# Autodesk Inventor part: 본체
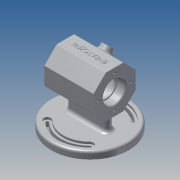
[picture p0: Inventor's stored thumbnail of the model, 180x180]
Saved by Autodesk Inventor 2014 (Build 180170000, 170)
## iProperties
Created: 2017-06
Part Number: 본체
Material: 알루미늄 6061
Document SubType Name: Modeling
Designer: SCD-A14
Density: 2.71 g/cm^3
Appearance: 알루미늄 - 평지
Mass: 562.54 g
Surface Area: 565.529 cm^2
Volume: 207.579 cm^3
Author: SCD-A14
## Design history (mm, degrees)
sketch "스케치1"
  geometry: C1 r 55 at (0, 0); 1 further point
  constraints: 1 centre point, 1 coincident
  dimensions: "d0" = 110 diameter of C1
extrude "돌출1" new body sketch "스케치1" distance "d1" = 10; taper "d2" = 0 deg
sketch "스케치2"
  geometry: L1 (-30, 49.574)-(-30, 74.426); L2 (-30, 74.426)-(-12.426, 92); L3 (-12.426, 92)-(12.426, 92); L4 (12.426, 92)-(30, 74.426); L5 (30, 74.426)-(30, 49.574); L6 (30, 49.574)-(12.426, 32); L7 (12.426, 32)-(-12.426, 32); L8 (-12.426, 32)-(-30, 49.574); L9 (-55, 0)-(55, 0) reference; C1 r 30 at (0, 62); 2 further points
  constraints: 16 end point, 1 centre point, 1 coincident, 1 tangent, 1 vertical, 1 vertical alignment, 17 other
  dimensions: "d3" = 60 diameter of C1; "d4" = 62 distance from line of L9 point (0, 62)
extrude "돌출2" join sketch "스케치2" stored distance "d5" = 70; taper "d6" = 0 deg
sketch "스케치3"
  geometry: L1 (24, 5)-(-24, 5); L2 (-24, 5)-(-24, -5); L3 (-24, -5)-(24, -5); L4 (24, -5)-(24, 5); L5 (24, 5)-(-24, -5); C1 r 5 at (24, 0); C2 r 5 at (-24, 0); 2 further points
  constraints: 10 end point, 3 midpoint, 2 centre point, 2 parallel, 1 coincident, 1 horizontal, 1 perpendicular
  dimensions: "d7" = 48 distance between parallel lines of L2 L4; "d9" = 10 diameter of C1; "d10" = 10 diameter of C2; "d11" = 10 distance between parallel lines of L3 L1
extrude "돌출3" join sketch "스케치3" stored distance "d12" = 70; taper "d13" = 0 deg
sketch "스케치4"
  geometry: L1 (0, 55)-(0, -55) reference; C1 r 16 at (62, 0); 2 further points
  constraints: 1 centre point, 1 horizontal alignment, 1 midpoint
  dimensions: "d14" = 32 diameter of C1; "d15" = 62 distance from line of L1 C1.centre
extrude "돌출4" cut sketch "스케치4" distance "d16" = 12; taper "d17" = 0 deg
sketch "스케치5"
  geometry: C1 r 16 at (0, 0) reference; C2 r 14 at (0, 0); 1 further point
  constraints: 1 centre point, 1 coincident
  dimensions: "d18" = 28 diameter of C2
extrude "돌출5" cut sketch "스케치5" distance "d19" = 3; taper "d20" = 0 deg
sketch "스케치6"
  geometry: C1 r 14 at (-62, 0) reference; C2 r 16 at (-62, 0); 1 further point
  constraints: 1 centre point, 1 coincident
  dimensions: "d21" = 32 diameter of C2
extrude "돌출6" cut sketch "스케치6" distance "d22" = 12; taper "d23" = 0 deg
sketch "스케치7"
  geometry: C1 r 16 at (0, 0) reference; C2 r 16 at (0, 0) reference; C3 r 14 at (0, 0); 1 further point
  constraints: 1 centre point, 1 coincident
  dimensions: "d24" = 28 diameter of C3
extrude "돌출7" cut sketch "스케치7" distance "d25" = 3; taper "d26" = 0 deg
sketch "스케치8"
  geometry: C1 r 14 at (0, 0) reference; C2 r 25 at (0, 0); 1 further point
  constraints: 1 centre point, 1 coincident
  dimensions: "d27" = 50 diameter of C2
extrude "돌출8" cut sketch "스케치8" distance "d28" = 40; taper "d29" = 0 deg
sketch "스케치9"
  geometry: L1 (0, 62)-(0, -16.548); L2 (0, 62)-(26.163, 88.163); L3 (30, 74.426)-(12.426, 92) reference; C1 r 16 at (0, 62) reference; 2 further points
  constraints: 4 end point, 1 coincident, 1 vertical
  dimensions: "d30" = 45 deg angle of L2 L1; "d31" = 7 distance from line of L2.end L3
node "작업 평면1"
sketch "스케치10"
  geometry: C1 r 8 at (0, 0); 2 further points
  constraints: 1 centre point, 1 coincident
  dimensions: "d32" = 16 diameter of C1
extrude "돌출9" join sketch "스케치10" stored distance "d33" = 40; taper "d34" = 0 deg
sketch "스케치11"
  geometry: C1 r 8 at (0, 0) reference; C2 r 4 at (0, 0); 1 further point
  constraints: 1 centre point, 1 coincident
  dimensions: "d35" = 8 diameter of C2
extrude "돌출10" cut sketch "스케치11" stored distance "d36" = 40; taper "d37" = 0 deg
sketch "스케치12" dims "d38" = 10, "d39" = 10
  geometry: L1 (0, 0)-(0, 65.936); L2 (-30.406, 30.406)-(0, 0); L3 (30.406, 30.406)-(0, 0); C1 r 55 at (0, 0) reference; A1 r 48 centre (0, 0) between (33.941, 33.941) and (-33.941, 33.941); A2 r 38 centre (0, 0) between (26.87, 26.87) and (-26.87, 26.87); 2 further points
  constraints: 6 end point, 4 point on circle, 2 centre point, 2 coincident, 2 point on line, 1 vertical, 9 other
  dimensions: "d40" = 96 diameter of A1; "d43" = 45 deg angle of L1 L2; "d44" = 45 deg angle of L3 L1; "d47" = 76 diameter of A2; "d48" = 10 radial gap between concentric circles of A2 A1
extrude "돌출11" cut sketch "스케치12" distance "d49" = 3; taper "d50" = 0 deg
sketch "스케치13"
  geometry: A1 r 48 centre (0, 0) between (33.941, 33.941) and (-33.941, 33.941); A2 r 38 centre (0, 0) between (26.87, 26.87) and (-26.87, 26.87); A3 r 5 centre (30.406, 30.406) between (26.87, 26.87) and (33.941, 33.941) reference; A4 r 5 centre (-30.406, 30.406) between (-26.87, 26.87) and (-33.941, 33.941) reference; 2 further points
  constraints: 8 point on circle, 2 centre point, 2 coincident
  dimensions: "d51" = 96 diameter of A1; "d52" = 76 diameter of A2
extrude "돌출12" cut sketch "스케치13" distance "d53" = 3; taper "d54" = 0 deg
sketch "스케치16"
  geometry: A1 r 5 centre (-30.406, 30.406) between (-33.941, 33.941) and (-26.87, 26.87) reference; A2 r 38 centre (0, 0) between (26.87, 26.87) and (-26.87, 26.87) reference; A3 r 5 centre (30.406, 30.406) between (26.87, 26.87) and (33.941, 33.941) reference; A4 r 48 centre (0, 0) between (33.941, 33.941) and (-33.941, 33.941) reference; A5 r 2 centre (30.406, 30.406) between (28.991, 28.991) and (31.82, 31.82); A6 r 41 centre (0, 0) between (28.991, 28.991) and (-28.991, 28.991); A7 r 45 centre (0, 0) between (31.82, 31.82) and (-31.82, 31.82); A8 r 2 centre (-30.406, 30.406) between (-28.991, 28.991) and (-31.82, 31.82); 1 further point
  constraints: 8 point on circle, 4 centre point, 4 coincident
  dimensions: "d57" = 4 diameter of A5; "d59" = 82 diameter of A6; "d60" = 90 diameter of A7; "d61" = 4 diameter of A8
extrude "돌출14" cut sketch "스케치16" stored distance "d64" = 3; taper "d65" = 0 deg
sketch "스케치17"
  geometry: L1 (70, -17.574)-(0, -17.574) reference; L2 (0, 0)-(0, 24.853) reference; L3 (70, 24.853)-(70, 0) reference; 2 further points
  constraints: 1 other
  dimensions: "d93" = 30 distance from line of L1 point (35, 12.426); "d94" = 35 distance from line of L3 point (35, 12.426)
fillet "모깎기1" dims "d70" = 3
fillet "모깎기2" dims "d71" = 1
fillet "모깎기3" dims "d72" = 3
fillet "모깎기4" dims "d73" = 3
fillet "모깎기5" dims "d74" = 5
chamfer "모따기1" distance "d75" = 1; stored, may be unused: second distance "d76" = 2, angle "d77" = 45 deg
fillet "모깎기6" dims "d78" = 0.3
sketch "스케치18" dims "d79" = 46
  geometry: L1 (-62, 0)-(-85, 0); C1 r 17 at (-62, 0) reference; C2 r 14 at (-62, 0) reference; 3 further points
  constraints: 2 coincident, 2 end point, 1 horizontal, 1 horizontal alignment, 2 other
hole "구멍1" sketch "스케치18" at (-85, 0) diameter "d80" = 3.242; stored, may be unused: countersink angle "d84" = 90 deg, drill point angle "d86" = 118 deg; dims "d81" = 8, "d82" = 4, "d83" = 2, "d85" = 10
chamfer "모따기2" distance "d90" = 1; stored, may be unused: second distance "d91" = 2, angle "d92" = 45 deg
feature "엠보싱2" dims "d95" = 0.5, "d96" = 0
node "솔리드1"
mirror "대칭1"
mirror "대칭2"
pattern_circular "원형 패턴1" dims angle "d88" = 360 deg
mirror "대칭3"
node "투영된 루프1"
node "투영된 루프2"
node "투영된 루프3"
node "투영된 루프4"
node "투영된 루프5"
node "투영된 루프7"
